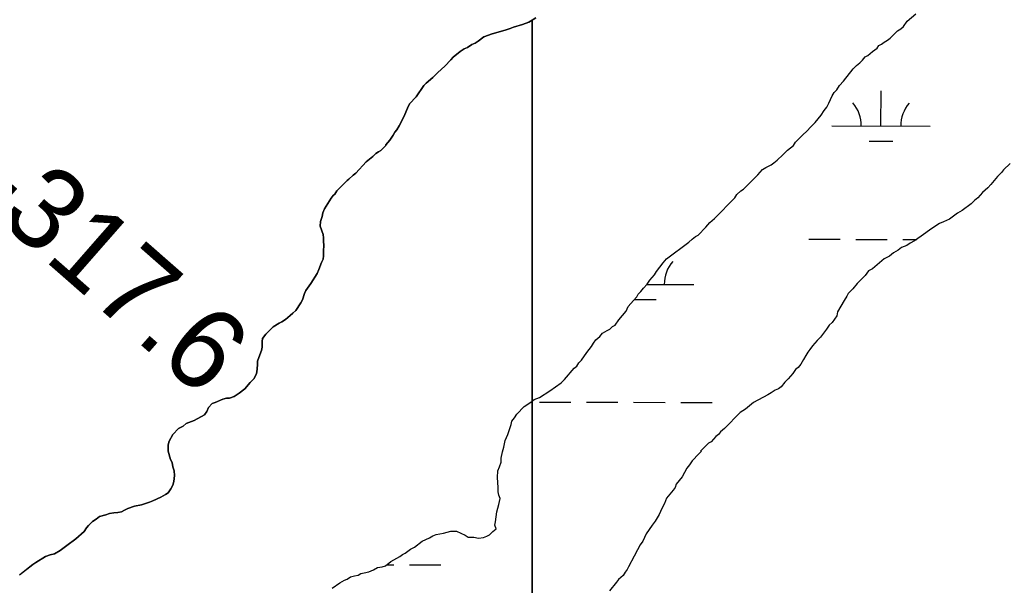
# Model space of a CAD drawing. Extents: x 3172297 to 3210190, y 958463 to 983887.
# Drawn here: x 3190887 to 3191893, y 964528 to 965104 of the extents above; entities that cross this region are included whole.
import ezdxf

# ---------------------------------------------------------------- set-up
doc = ezdxf.new("R2010")
doc.units = 0
for name, color, linetype in [('V-RIVR-RANG-IDEN', 7, 'Continuous'), ('V-SITE-VEGE', 7, 'Continuous'), ('V-TOPO-SHOR', 7, 'Continuous'), ('V-WETL-SWMP', 7, 'Continuous')]:
    doc.layers.add(name, color=color, linetype=linetype)

msp = doc.modelspace()

# ---------------------------------------------------------------- linework, layer by layer
at = {"layer": 'V-SITE-VEGE'}
for p, q in [((3191399.4, 965099.3), (3191390.1, 965096.5)), ((3191405.9, 965101.7), (3191399.4, 965099.3)), ((3191409, 965103.6), (3191405.9, 965101.7)), ((3191412.8, 965105.9), (3191409, 965103.6)), ((3191409, 965103.6), (3191409, 964274.1)), ((3191409, 964274.1), (3191409, 965103.6)), ((3191368.4, 965089.9), (3191359.8, 965086.8)), ((3191376.7, 965092), (3191368.4, 965089.9)), ((3191382.5, 965093.7), (3191376.7, 965092)), ((3191386.6, 965095.1), (3191382.5, 965093.7)), ((3191390.1, 965096.5), (3191386.6, 965095.1)), ((3191347.8, 965078.8), (3191343.3, 965076)), ((3191350.9, 965080.2), (3191347.8, 965078.8)), ((3191354, 965082.3), (3191350.9, 965080.2)), ((3191359.8, 965086.8), (3191354, 965082.3)), ((3191335.7, 965071.9), (3191328.5, 965066)), ((3191339.9, 965074.6), (3191335.7, 965071.9)), ((3191343.3, 965076), (3191339.9, 965074.6)), ((3191326.1, 965063.2), (3191320, 965056.7)), ((3191328.5, 965066), (3191326.1, 965063.2)), ((3191313.1, 965050.4), (3191307.9, 965045.3)), ((3191320, 965056.7), (3191313.1, 965050.4)), ((3191301.1, 965039.4), (3191298.7, 965037)), ((3191307.9, 965045.3), (3191301.1, 965039.4)), ((3191298.7, 965037), (3191290.8, 965025.6)), ((3191284.3, 965018.3), (3191282.2, 965014.2)), ((3191290.8, 965025.6), (3191284.3, 965018.3)), ((3191279.5, 965007.6), (3191277.1, 965002.5)), ((3191282.2, 965014.2), (3191279.5, 965007.6)), ((3191277.1, 965002.5), (3191273.6, 964995.9)), ((3191269.2, 964989.7), (3191267.5, 964986.6)), ((3191271.2, 964992.1), (3191269.2, 964989.7)), ((3191273.6, 964995.9), (3191271.2, 964992.1)), ((3191264.1, 964981.4), (3191259.9, 964976.6)), ((3191267.5, 964986.6), (3191264.1, 964981.4)), ((3191250, 964967.9), (3191246.9, 964964.8)), ((3191252.4, 964969.7), (3191250, 964967.9)), ((3191254.8, 964971), (3191252.4, 964969.7)), ((3191257.5, 964973.5), (3191254.8, 964971)), ((3191259.9, 964975.9), (3191257.5, 964973.5)), ((3191259.9, 964976.6), (3191259.9, 964975.9)), ((3191240, 964959.3), (3191229.4, 964947.9)), ((3191246.9, 964964.8), (3191240, 964959.3)), ((3191229.4, 964947.9), (3191226.6, 964945.8)), ((3191220.8, 964940.3), (3191210.1, 964929.9)), ((3191222.5, 964941.7), (3191220.8, 964940.3)), ((3191226.6, 964945.8), (3191222.5, 964941.7)), ((3191208.1, 964926.5), (3191206.4, 964925.1)), ((3191210.1, 964929.9), (3191208.1, 964926.5)), ((3191204.3, 964922.3), (3191197.5, 964911.6)), ((3191206.4, 964925.1), (3191204.3, 964922.3)), ((3191195.7, 964907.5), (3191195.1, 964903.7)), ((3191197.5, 964911.6), (3191195.7, 964907.5)), ((3191193.4, 964898.5), (3191193, 964894)), ((3191195.1, 964903.7), (3191193.4, 964898.5)), ((3191193, 964894), (3191196.2, 964885.4)), ((3191196.2, 964885.4), (3191196.5, 964882)), ((3191196.5, 964882), (3191196.5, 964877.2)), ((3191196.5, 964877.2), (3191196.9, 964875.4)), ((3191196.9, 964875.4), (3191196.6, 964867.2)), ((3191196.6, 964867.2), (3191196.6, 964863.7)), ((3191194.5, 964856.8), (3191191.8, 964849.6)), ((3191196.2, 964860.3), (3191194.5, 964856.8)), ((3191196.6, 964863.7), (3191196.2, 964860.3)), ((3191191.8, 964849.6), (3191190.1, 964845.8)), ((3191190.1, 964845.8), (3191183.6, 964835.4)), ((3191178.4, 964828.2), (3191177.1, 964825.1)), ((3191183.6, 964835.4), (3191178.4, 964828.2)), ((3191173.3, 964815.8), (3191168.5, 964807.8)), ((3191175, 964818.9), (3191173.3, 964815.8)), ((3191177.1, 964825.1), (3191175, 964818.9)), ((3191168.5, 964807.8), (3191165.4, 964805.1)), ((3191154.1, 964796.4), (3191151.3, 964795)), ((3191157.9, 964798.8), (3191154.1, 964796.4)), ((3191162.7, 964803), (3191157.9, 964798.8)), ((3191165.4, 964805.1), (3191162.7, 964803)), ((3191145.1, 964791.2), (3191137.9, 964784)), ((3191151.3, 964795), (3191145.1, 964791.2)), ((3191134.5, 964779.5), (3191134.2, 964776.4)), ((3191134.2, 964776.4), (3191134.2, 964770.5)), ((3191137.9, 964784), (3191134.5, 964779.5)), ((3191133.5, 964767.1), (3191131.5, 964762.9)), ((3191134.2, 964770.5), (3191133.5, 964767.1)), ((3191131.5, 964762.9), (3191129.4, 964756.4)), ((3191129.4, 964756.4), (3191129.4, 964753.3)), ((3191128.8, 964748.1), (3191128.4, 964743.6)), ((3191129.4, 964753.3), (3191128.8, 964748.1)), ((3191125.7, 964738.5), (3191121.9, 964734.7)), ((3191128.4, 964743.6), (3191125.7, 964738.5)), ((3191116.4, 964728.1), (3191110.6, 964723.6)), ((3191121.9, 964734.7), (3191116.4, 964728.1)), ((3191094.1, 964717.7), (3191086.2, 964714.2)), ((3191097.8, 964718.7), (3191094.1, 964717.7)), ((3191100.9, 964718.7), (3191097.8, 964718.7)), ((3191105.4, 964720.5), (3191100.9, 964718.7)), ((3191110.6, 964723.6), (3191105.4, 964720.5)), ((3191077.6, 964705.2), (3191075.2, 964701.8)), ((3191079.3, 964709), (3191077.6, 964705.2)), ((3191083.1, 964713.2), (3191079.3, 964709)), ((3191086.2, 964714.2), (3191083.1, 964713.2)), ((3191064.9, 964695.9), (3191056.6, 964692.8)), ((3191075.2, 964701.8), (3191064.9, 964695.9)), ((3191048.7, 964687.6), (3191042.9, 964681.7)), ((3191053.5, 964690), (3191048.7, 964687.6)), ((3191056.6, 964692.8), (3191053.5, 964690)), ((3191042.9, 964681.7), (3191039.4, 964674.8)), ((3191039.4, 964674.8), (3191038.4, 964671)), ((3191038.4, 964671), (3191038.4, 964664.5)), ((3191038.4, 964664.5), (3191040.5, 964656.2)), ((3191040.5, 964656.2), (3191042.3, 964653.1)), ((3191042.3, 964653.1), (3191043, 964648.6)), ((3191043, 964648.6), (3191044.4, 964644.5)), ((3191044.7, 964640), (3191044, 964633.8)), ((3191044.4, 964644.5), (3191044.7, 964640)), ((3191041, 964626.2), (3191038.2, 964622.1)), ((3191043, 964630), (3191041, 964626.2)), ((3191044, 964633.8), (3191043, 964630)), ((3191030.7, 964617.9), (3191022.8, 964614.1)), ((3191035.5, 964620.4), (3191030.7, 964617.9)), ((3191038.2, 964622.1), (3191035.5, 964620.4)), ((3190993.9, 964604.7), (3190990.8, 964603)), ((3190997, 964606.1), (3190993.9, 964604.7)), ((3191003.8, 964608.6), (3190997, 964606.1)), ((3191011.1, 964610), (3191003.8, 964608.6)), ((3191019.3, 964612.7), (3191011.1, 964610)), ((3191022.8, 964614.1), (3191019.3, 964612.7)), ((3190965, 964595.3), (3190961.2, 964592.9)), ((3190968.4, 964598.1), (3190965, 964595.3)), ((3190974.6, 964599.8), (3190968.4, 964598.1)), ((3190978.4, 964601.2), (3190974.6, 964599.8)), ((3190982.8, 964601.9), (3190978.4, 964601.2)), ((3190987, 964602.3), (3190982.8, 964601.9)), ((3190990.8, 964603), (3190987, 964602.3)), ((3190955, 964586.4), (3190952.6, 964582.9)), ((3190957.1, 964588.8), (3190955, 964586.4)), ((3190961.2, 964592.9), (3190957.1, 964588.8)), ((3190944.3, 964575.3), (3190935.1, 964568.7)), ((3190952.6, 964582.9), (3190944.3, 964575.3)), ((3190935.1, 964568.7), (3190928.2, 964563.5)), ((3190913.4, 964557.3), (3190903.4, 964551.1)), ((3190918.2, 964559), (3190913.4, 964557.3)), ((3190922.4, 964560.1), (3190918.2, 964559)), ((3190928.2, 964563.5), (3190922.4, 964560.1)), ((3190900.3, 964549.3), (3190887, 964538.6)), ((3190903.4, 964551.1), (3190900.3, 964549.3))]:
    msp.add_line(p, q, dxfattribs=at)
at = {"layer": 'V-TOPO-SHOR'}
for points in [[(3191075.2, 964701.8), (3191077.6, 964705.2), (3191079.3, 964709), (3191083.1, 964713.2), (3191086.2, 964714.2), (3191094.1, 964717.7), (3191097.8, 964718.7), (3191100.9, 964718.7), (3191105.4, 964720.5), (3191110.6, 964723.6), (3191116.4, 964728.1), (3191121.9, 964734.7), (3191125.7, 964738.5), (3191128.4, 964743.6), (3191128.8, 964748.1), (3191129.4, 964753.3), (3191129.4, 964756.4), (3191131.5, 964762.9), (3191133.5, 964767.1), (3191134.2, 964770.5), (3191134.2, 964776.4), (3191134.5, 964779.5), (3191137.9, 964784), (3191145.1, 964791.2), (3191151.3, 964795), (3191154.1, 964796.4), (3191157.9, 964798.8), (3191162.7, 964803), (3191165.4, 964805.1), (3191168.5, 964807.8), (3191173.3, 964815.8), (3191175, 964818.9), (3191177.1, 964825.1), (3191178.4, 964828.2), (3191183.6, 964835.4), (3191190.1, 964845.8), (3191191.8, 964849.6), (3191194.5, 964856.8), (3191196.2, 964860.3), (3191196.6, 964863.7), (3191196.6, 964867.2), (3191196.9, 964875.4), (3191196.5, 964877.2), (3191196.5, 964882), (3191196.2, 964885.4), (3191193, 964894), (3191193.4, 964898.5), (3191195.1, 964903.7), (3191195.7, 964907.5), (3191197.5, 964911.6), (3191204.3, 964922.3), (3191206.4, 964925.1), (3191208.1, 964926.5), (3191210.1, 964929.9), (3191220.8, 964940.3), (3191222.5, 964941.7), (3191226.6, 964945.8), (3191229.4, 964947.9), (3191240, 964959.3), (3191246.9, 964964.8), (3191250, 964967.9), (3191252.4, 964969.7), (3191254.8, 964971), (3191257.5, 964973.5), (3191259.9, 964975.9), (3191259.9, 964976.6), (3191264.1, 964981.4), (3191267.5, 964986.6), (3191269.2, 964989.7), (3191271.2, 964992.1), (3191273.6, 964995.9), (3191277.1, 965002.5), (3191279.5, 965007.6), (3191282.2, 965014.2), (3191284.3, 965018.3), (3191290.8, 965025.6), (3191298.7, 965037), (3191301.1, 965039.4), (3191307.9, 965045.3), (3191313.1, 965050.4), (3191320, 965056.7), (3191326.1, 965063.2), (3191328.5, 965066), (3191335.7, 965071.9), (3191339.9, 965074.6), (3191343.3, 965076), (3191347.8, 965078.8), (3191350.9, 965080.2), (3191354, 965082.3), (3191359.8, 965086.8), (3191368.4, 965089.9), (3191376.7, 965092), (3191382.5, 965093.7), (3191386.6, 965095.1), (3191390.1, 965096.5), (3191399.4, 965099.3), (3191405.9, 965101.7), (3191412.8, 965105.9)], [(3190886.9, 964538.6), (3190900.3, 964549.3), (3190903.4, 964551.1), (3190913.4, 964557.3), (3190918.2, 964559), (3190922.4, 964560.1), (3190928.2, 964563.5), (3190935.1, 964568.7), (3190944.3, 964575.3), (3190952.6, 964582.9), (3190955, 964586.4), (3190957.1, 964588.8), (3190961.2, 964592.9), (3190965, 964595.3), (3190968.4, 964598.1), (3190974.6, 964599.8), (3190978.4, 964601.2), (3190982.8, 964601.9), (3190987, 964602.3), (3190990.8, 964603), (3190993.9, 964604.7), (3190997, 964606.1), (3191003.8, 964608.6), (3191011.1, 964610), (3191019.3, 964612.7), (3191022.8, 964614.1), (3191030.7, 964617.9), (3191035.5, 964620.4), (3191038.2, 964622.1), (3191041, 964626.2), (3191043, 964630), (3191044, 964633.8), (3191044.7, 964640), (3191044.4, 964644.5), (3191043, 964648.6), (3191042.3, 964653.1), (3191040.5, 964656.2), (3191038.4, 964664.5), (3191038.4, 964671), (3191039.4, 964674.8), (3191042.9, 964681.7), (3191048.7, 964687.6), (3191053.5, 964690), (3191056.6, 964692.8), (3191064.9, 964695.9), (3191075.2, 964701.8)]]:
    msp.add_lwpolyline(points, dxfattribs=at)
at = {"layer": 'V-WETL-SWMP'}
for p, q in [((3191764.5, 964995.8), (3191764.6, 965031.8)), ((3191714.5, 964995.9), (3191814.5, 964995.7)), ((3191752.5, 964980.4), (3191776.5, 964980.3)), ((3191690.9, 964880.5), (3191722.9, 964880.5)), ((3191738.9, 964880.4), (3191770.9, 964880.3)), ((3191786.9, 964880.3), (3191800.9, 964880.3)), ((3191526.1, 964834.5), (3191573.7, 964834.4)), ((3191513.3, 964819.1), (3191535.6, 964819.1)), ((3191416.5, 964714.7), (3191448.5, 964714.6)), ((3191464.5, 964714.6), (3191496.5, 964714.5)), ((3191512.5, 964714.5), (3191544.5, 964714.4)), ((3191560.5, 964714.4), (3191592.5, 964714.3)), ((3191260.8, 964548.9), (3191268.1, 964548.9)), ((3191284.1, 964548.9), (3191316.1, 964548.8))]:
    msp.add_line(p, q, dxfattribs=at)
for points in [[(3191745.7, 965063), (3191748.4, 965066.3), (3191751.1, 965067.7), (3191755.8, 965071.7), (3191760.5, 965075.1), (3191762.5, 965077.8), (3191765.2, 965079.2), (3191767.8, 965081.2), (3191771.2, 965083.2), (3191773.9, 965085.2), (3191781.3, 965092.7), (3191784.6, 965094.7), (3191787.3, 965097.4), (3191791.3, 965102.8), (3191800, 965110.2)], [(3191349.6, 964577.2), (3191354.4, 964575.9), (3191359.7, 964576.6), (3191363.1, 964578), (3191365.8, 964579.3), (3191369.1, 964582.7), (3191372.5, 964585.4), (3191371.1, 964589.4), (3191371.8, 964592.8), (3191373.1, 964602.9), (3191375.1, 964610.3), (3191376.4, 964616.4), (3191375.1, 964619.7), (3191374.4, 964623.1), (3191374.4, 964627.8), (3191373.7, 964637.9), (3191374.3, 964644.6), (3191375.7, 964648.6), (3191377.7, 964653.4), (3191377.6, 964657.4), (3191379, 964664.1), (3191380.3, 964668.8), (3191381.6, 964675.6), (3191384.3, 964681.6), (3191387.6, 964691.7), (3191388.3, 964695.1), (3191391, 964698.5), (3191393.6, 964702.5), (3191401, 964710), (3191407.7, 964714.7), (3191411.1, 964717.4), (3191416.5, 964719.4), (3191427.2, 964726.2), (3191438.6, 964734.3), (3191442, 964737.7), (3191452, 964749.1), (3191454.7, 964751.2), (3191456.7, 964754.5), (3191459.4, 964757.2), (3191464.8, 964765.3), (3191469.5, 964771.4), (3191471.5, 964774.8), (3191474.1, 964778.1), (3191478.2, 964781.5), (3191480.8, 964784.9), (3191485.5, 964787.6), (3191488.2, 964789), (3191490.9, 964791.7), (3191493.6, 964793), (3191497.6, 964798.4), (3191505, 964807.2), (3191507, 964811.9), (3191512.4, 964818), (3191515.7, 964822), (3191517, 964824.7), (3191519.7, 964827.4), (3191522.4, 964830.8), (3191526.4, 964834.8), (3191529.1, 964838.9), (3191533.8, 964844.3), (3191535.8, 964847.6), (3191542.5, 964856.4), (3191545.9, 964860.5), (3191568.7, 964877.4), (3191572, 964880.7), (3191575.4, 964883.4), (3191578.1, 964884.8), (3191586.1, 964892.9), (3191590.1, 964897.6), (3191594.8, 964901.7), (3191615.6, 964922.6), (3191617.6, 964926), (3191621.7, 964930), (3191624.3, 964931.4), (3191639.1, 964946.2), (3191643.8, 964951.6), (3191647.2, 964953.6), (3191652.5, 964956.3), (3191655.2, 964958.4), (3191658.6, 964961.1), (3191664.6, 964966.5), (3191669.3, 964971.2), (3191675.3, 964975.9), (3191677.3, 964979.3), (3191684.7, 964986.7), (3191689.4, 964990.8), (3191692.8, 964994.8), (3191697.5, 964999.6), (3191703.5, 965007), (3191706.8, 965011.7), (3191709.5, 965015.1), (3191711.5, 965019.1), (3191714.9, 965026.5), (3191716.9, 965029.9), (3191719.6, 965032.6), (3191722.2, 965037.3), (3191726.3, 965041.4), (3191736.3, 965054.2), (3191739.7, 965057.6), (3191743, 965060.3), (3191745.7, 965063)], [(3191896.1, 964957.8), (3191889.4, 964951.1), (3191887.4, 964948.4), (3191883.3, 964944.3), (3191876.6, 964936.2), (3191873.3, 964932.8), (3191867.9, 964928.1), (3191863.2, 964922.7), (3191859.9, 964920), (3191856.5, 964916.6), (3191847.1, 964909.9), (3191842.4, 964907.2), (3191834.4, 964901.1), (3191828.3, 964898.4), (3191824.3, 964896.4), (3191816.2, 964891.6), (3191805.5, 964883.5), (3191798.8, 964878.8), (3191794.1, 964876.7), (3191790.7, 964874), (3191785.3, 964872), (3191782, 964869.3), (3191777.3, 964866.6), (3191773.3, 964863.2), (3191767.9, 964860.5), (3191755.8, 964850.4), (3191751.8, 964848.3), (3191748.4, 964843.6), (3191740.4, 964835.5), (3191735.7, 964830.1), (3191731, 964825.4), (3191729.7, 964822.7), (3191727, 964818), (3191720.3, 964806.5), (3191719.6, 964802.5), (3191714.9, 964795.7), (3191711.6, 964793), (3191708.9, 964789), (3191702.9, 964780.9), (3191699.5, 964777.5), (3191694.8, 964772.1), (3191692.2, 964768.1), (3191690.1, 964765.4)], [(3191690.1, 964765.4), (3191688.1, 964762), (3191685.5, 964758), (3191682.8, 964753.3), (3191680.1, 964749.9), (3191677.4, 964747.9), (3191674.7, 964743.8), (3191670.1, 964738.4), (3191666.7, 964735), (3191662.7, 964730.3), (3191660, 964728.3), (3191656.6, 964726.9), (3191652.6, 964724.2), (3191649.2, 964722.2), (3191634.5, 964714.1), (3191626.4, 964707.3), (3191621.1, 964703.9), (3191605, 964687.7), (3191600.9, 964684.4), (3191598.9, 964681.7), (3191596.2, 964679.6), (3191591.5, 964674.2), (3191588.9, 964672.9), (3191580.8, 964664.8), (3191581.5, 964664.8), (3191578.8, 964662.1), (3191572.1, 964654.7), (3191569.4, 964650.6), (3191566.7, 964647.3), (3191562.1, 964638.5), (3191556, 964631.1), (3191554.7, 964627.7), (3191552.7, 964625), (3191546, 964616.9), (3191544, 964611.5), (3191541.3, 964606.1), (3191538.6, 964600.1), (3191534.6, 964593.3), (3191531.3, 964589.3), (3191525.2, 964580.5), (3191521.9, 964573.1), (3191519.2, 964569.1), (3191516.5, 964564.3), (3191513.2, 964557.6), (3191507.2, 964546.8), (3191505.8, 964544.1), (3191503.8, 964541.4), (3191501.8, 964538), (3191497.1, 964534), (3191495.1, 964531.3), (3191487.8, 964522.5)], [(3191205.2, 964525), (3191213.2, 964530.4), (3191217.9, 964533.1), (3191220.6, 964534.4), (3191224, 964536.5), (3191228, 964537.8), (3191232, 964538.5), (3191234.7, 964539.9), (3191238.1, 964540.6), (3191242.8, 964541.9), (3191247.5, 964543.9), (3191251.5, 964546), (3191256.2, 964546.7), (3191259.6, 964548), (3191265, 964552.1), (3191274.4, 964557.5), (3191277, 964559.5), (3191279.7, 964560.9), (3191285.1, 964564.9), (3191289.1, 964567), (3191297.2, 964573), (3191304.6, 964576.4), (3191307.9, 964578.5), (3191311.3, 964579.8), (3191318.7, 964581.2), (3191326.1, 964583.2), (3191332.1, 964583.2), (3191340.9, 964579.2), (3191342.9, 964577.9), (3191343.6, 964577.2), (3191349.6, 964577.2)]]:
    msp.add_lwpolyline(points, dxfattribs=at)
for centre, start, end in [((3191709.3, 964996.4), 359.0865, 40.6302), ((3191819.8, 964996.1), 139.0865, 180.6302), ((3191578.9, 964834.9), 139.0865, 180.6302)]:
    msp.add_arc(centre, 35.2, start, end, dxfattribs=at)

# ---------------------------------------------------------------- texts
at = {"layer": 'V-RIVR-RANG-IDEN'}
msp.add_text('R-317.6', height=83, rotation=318.7698, dxfattribs=at).set_placement((3190775.9, 964978.3))

doc.saveas('drawing.dxf')
